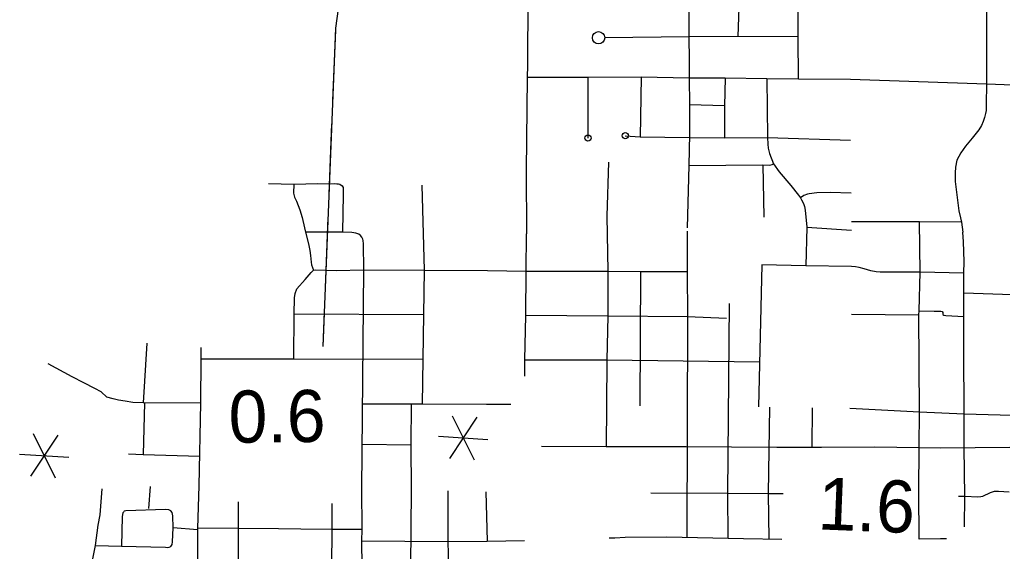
# Model space of a CAD drawing. Extents: x 1366406 to 1373462, y 376856 to 381998.
# Drawn here: x 1369241.5 to 1369331.1, y 379974.8 to 380023.3 of the extents above; entities that cross this region are included whole.
import ezdxf

# ---------------------------------------------------------------- set-up
doc = ezdxf.new("R2010")
doc.units = 0
for name, color, linetype in [('33', 7, 'Continuous'), ('43', 7, 'Continuous'), ('48', 7, 'Continuous')]:
    doc.layers.add(name, color=color, linetype=linetype)

msp = doc.modelspace()

# ---------------------------------------------------------------- linework, layer by layer
at = {"layer": '33'}
for points in [[(1369307.085, 380042.984), (1369307.105, 380040.757), (1369307.055, 380036.923), (1369307.016, 380032.818), (1369307.052, 380028.647), (1369307.064, 380024.428), (1369306.983, 380021.764)], [(1369329.728, 380043.361), (1369329.705, 380038.326), (1369329.648, 380031.144), (1369329.645, 380024.267), (1369329.639, 380017.427), (1369329.612, 380015.619), (1369329.585, 380015.032), (1369329.538, 380014.76), (1369329.443, 380014.38), (1369329.319, 380014.032), (1369329.164, 380013.665), (1369328.917, 380013.285), (1369328.33, 380012.508), (1369327.721, 380011.784), (1369327.277, 380011.182), (1369326.929, 380010.492), (1369326.794, 380009.874), (1369326.761, 380009.365), (1369326.778, 380008.563), (1369327.117, 380005.879), (1369327.25, 380005.241), (1369327.357, 380004.838), (1369327.484, 380003.946)], [(1369312.516, 380017.887), (1369312.458, 380021.753), (1369312.485, 380024.346), (1369312.503, 380028.563), (1369312.438, 380032.761), (1369312.54, 380036.802), (1369312.639, 380040.705)], [(1369302.478, 380028.724), (1369302.547, 380017.974), (1369302.578, 380015.537), (1369302.579, 380012.87), (1369302.509, 380010.019), (1369302.374, 380004.347)], [(1369287.851, 380025.364), (1369287.799, 380019.154), (1369287.787, 380018.052), (1369287.702, 380009.57), (1369287.716, 380003.802)], [(1369312.458, 380021.753), (1369306.983, 380021.764), (1369302.532, 380021.758), (1369294.852, 380021.665)], [(1369332.066, 380017.346), (1369329.639, 380017.427), (1369317.254, 380017.859), (1369312.516, 380017.887), (1369309.619, 380017.934), (1369305.829, 380017.977), (1369302.547, 380017.974), (1369298.155, 380018.056), (1369293.296, 380018.033), (1369291.822, 380018.041), (1369287.787, 380018.052)], [(1369293.296, 380018.033), (1369293.319, 380012.517)], [(1369298.155, 380018.056), (1369298.09, 380012.624)], [(1369305.829, 380017.977), (1369305.768, 380015.447), (1369305.77, 380012.533)], [(1369309.619, 380017.934), (1369309.684, 380012.561), (1369309.705, 380011.978), (1369309.743, 380011.595), (1369309.86, 380011.12), (1369310.23, 380010.162), (1369310.755, 380009.435), (1369311.814, 380008.21), (1369312.488, 380007.304), (1369312.676, 380007.058), (1369312.776, 380006.879), (1369312.969, 380006.542), (1369313.043, 380006.273), (1369313.114, 380005.953), (1369313.265, 380004.389)], [(1369305.768, 380015.447), (1369302.578, 380015.537)], [(1369296.72, 380012.731), (1369298.09, 380012.624), (1369302.57, 380012.561), (1369305.77, 380012.533), (1369309.684, 380012.561), (1369317.238, 380012.324)], [(1369295.183, 380010.333), (1369295.048, 380005.399), (1369295.133, 380000.376), (1369295.14, 379996.295), (1369295.053, 379992.297), (1369295.005, 379988.139), (1369294.988, 379984.395)], [(1369302.509, 380010.019), (1369309.266, 380010.075), (1369309.879, 380010.049), (1369310.103, 380010.096), (1369310.23, 380010.162)], [(1369309.266, 380010.075), (1369309.335, 380005.311)], [(1369264.217, 380008.363), (1369266.531, 380008.32), (1369268.699, 380008.378), (1369269.901, 380008.354), (1369270.224, 380008.364), (1369270.447, 380008.35), (1369270.6, 380008.351), (1369270.711, 380008.323), (1369270.916, 380008.178), (1369271.018, 380008.018), (1369271.023, 380007.762), (1369271.018, 380007.362), (1369270.972, 380003.936)], [(1369266.531, 380008.32), (1369266.51, 380007.494), (1369266.589, 380007.121), (1369266.77, 380006.752), (1369267.058, 380005.978), (1369267.294, 380005.269), (1369267.492, 380004.348), (1369267.579, 380003.944), (1369267.849, 380002.875), (1369267.998, 380002.266), (1369268.047, 380001.802), (1369268.102, 380001.215), (1369268.147, 380000.973), (1369268.307, 380000.489)], [(1369278.235, 379988.249), (1369278.302, 379992.353), (1369278.415, 380000.486), (1369278.213, 380008.213)], [(1369317.3, 380007.51), (1369315.379, 380007.57), (1369314.168, 380007.534), (1369313.486, 380007.439), (1369313.308, 380007.393), (1369313.001, 380007.295), (1369312.676, 380007.058)], [(1369313.265, 380004.389), (1369313.166, 380000.858)], [(1369313.265, 380004.389), (1369317.331, 380004.113)], [(1369327.357, 380004.838), (1369323.535, 380004.885), (1369317.328, 380004.881)], [(1369323.502, 379975.947), (1369323.473, 379980.296), (1369323.498, 379984.334), (1369323.532, 379987.56), (1369323.473, 379996.4), (1369323.496, 379996.765), (1369323.572, 380000.29), (1369323.535, 380004.885)], [(1369272.759, 379973.466), (1369272.735, 379975.812), (1369272.757, 379976.834), (1369272.733, 379980.532), (1369272.895, 380000.506), (1369272.885, 380002.876), (1369272.833, 380003.176), (1369272.824, 380003.289), (1369272.709, 380003.48), (1369272.596, 380003.64), (1369272.446, 380003.762), (1369272.187, 380003.86), (1369271.803, 380003.925), (1369270.972, 380003.936), (1369267.579, 380003.944)], [(1369287.579, 379990.822), (1369287.565, 379992.295), (1369287.673, 379996.355), (1369287.691, 380000.394), (1369287.716, 380003.802)], [(1369302.365, 380004.038), (1369302.359, 380000.367), (1369302.389, 379996.232), (1369302.315, 379976.1)], [(1369327.63, 379977.063), (1369327.649, 379979.871), (1369327.595, 379984.312), (1369327.57, 379996.246), (1369327.577, 379998.403), (1369327.573, 380000.192), (1369327.596, 380001.278), (1369327.54, 380003.058), (1369327.484, 380003.946)], [(1369309.148, 380000.968), (1369308.85, 379988.01)], [(1369313.166, 380000.858), (1369309.148, 380000.968)], [(1369317.322, 380000.816), (1369313.166, 380000.858)], [(1369327.573, 380000.192), (1369323.572, 380000.29), (1369319.947, 380000.306), (1369319.588, 380000.329), (1369319.079, 380000.401), (1369318.472, 380000.602), (1369318.033, 380000.721), (1369317.695, 380000.776), (1369317.322, 380000.816)], [(1369266.53, 379992.38), (1369266.568, 379996.476), (1369266.594, 379997.961), (1369266.656, 379998.363), (1369266.804, 379998.772), (1369267.558, 379999.614), (1369268.115, 380000.274), (1369268.307, 380000.489), (1369268.523, 380000.507), (1369270.394, 380000.445), (1369272.895, 380000.506), (1369278.415, 380000.486), (1369284.184, 380000.451), (1369287.691, 380000.394), (1369295.133, 380000.376), (1369298.118, 380000.362), (1369302.359, 380000.367)], [(1369298.127, 380000.299), (1369298.118, 380000.362), (1369298.035, 379988.097)], [(1369327.577, 379998.403), (1369331.983, 379998.273), (1369342.02, 379997.853), (1369347.233, 379997.601), (1369352.351, 379997.429), (1369357.42, 379997.201), (1369362.517, 379996.954)], [(1369306.193, 379997.445), (1369306.031, 379980.155), (1369306.065, 379976.025)], [(1369278.358, 379996.408), (1369266.568, 379996.476)], [(1369305.946, 379996.071), (1369302.389, 379996.232), (1369295.14, 379996.295), (1369287.673, 379996.355)], [(1369317.327, 379996.474), (1369323.473, 379996.4)], [(1369323.496, 379996.765), (1369324.863, 379996.753), (1369325.272, 379996.735), (1369325.455, 379996.731), (1369325.579, 379996.715), (1369325.654, 379996.63), (1369325.665, 379996.446), (1369325.74, 379996.361), (1369325.93, 379996.341), (1369327.57, 379996.246)], [(1369253.127, 379993.825), (1369252.809, 379988.369)], [(1369258.06, 379993.431), (1369258.056, 379992.39), (1369258.015, 379988.358), (1369257.869, 379980.81)], [(1369258.015, 379988.358), (1369252.809, 379988.369), (1369251.867, 379988.404), (1369251.148, 379988.522), (1369250.566, 379988.624), (1369250.069, 379988.753), (1369249.476, 379988.893), (1369248.976, 379989.377), (1369248.407, 379989.679), (1369247.391, 379990.191), (1369246.332, 379990.75), (1369244.157, 379991.924)], [(1369258.056, 379992.39), (1369266.53, 379992.38), (1369278.302, 379992.353)], [(1369287.565, 379992.295), (1369295.053, 379992.297), (1369308.945, 379992.127)], [(1369252.931, 379988.386), (1369252.795, 379983.685)], [(1369286.301, 379988.244), (1369284.09, 379988.223), (1369278.235, 379988.249), (1369277.215, 379988.252), (1369272.796, 379988.266)], [(1369277.215, 379988.252), (1369277.183, 379984.563), (1369277.211, 379980.456), (1369277.154, 379973.425)], [(1369309.853, 379987.995), (1369309.735, 379980.132), (1369309.806, 379975.944)], [(1369313.763, 379984.334), (1369313.786, 379987.939)], [(1369317.177, 379987.891), (1369323.532, 379987.56), (1369327.583, 379987.394), (1369336.308, 379987.137)], [(1369272.766, 379984.615), (1369277.183, 379984.563)], [(1369289.104, 379984.44), (1369294.988, 379984.395), (1369302.28, 379984.388), (1369310.518, 379984.348), (1369314.593, 379984.331), (1369319.467, 379984.366), (1369325.448, 379984.276), (1369331.763, 379984.349), (1369332.303, 379984.314), (1369335.327, 379984.311), (1369338.659, 379984.311), (1369341.144, 379984.095), (1369343.947, 379983.711), (1369346.115, 379983.665), (1369348.882, 379983.67), (1369352.32, 379983.786)], [(1369251.453, 379983.729), (1369252.795, 379983.685), (1369257.953, 379983.515)], [(1369247.118, 379959.459), (1369247.735, 379970.162), (1369248.027, 379972.715), (1369248.165, 379973.858), (1369248.46, 379975.383), (1369248.714, 379977.22), (1369248.874, 379978.158), (1369249.077, 379980.553)], [(1369253.451, 379980.745), (1369253.272, 379978.753)], [(1369257.869, 379980.81), (1369257.757, 379976.943), (1369257.754, 379976.815), (1369257.755, 379973.597), (1369257.735, 379972.678), (1369257.745, 379970.699), (1369257.709, 379968.827), (1369257.653, 379964.775), (1369257.6, 379960.679), (1369257.6, 379959.637), (1369257.605, 379958.677)], [(1369280.566, 379980.347), (1369280.558, 379975.747), (1369280.604, 379973.422)], [(1369284.011, 379980.274), (1369284.138, 379975.778)], [(1369299.06, 379980.177), (1369306.031, 379980.155), (1369309.735, 379980.132), (1369311.109, 379980.119)], [(1369327.076, 379979.869), (1369327.649, 379979.871), (1369328.856, 379979.812), (1369329.106, 379979.838), (1369329.308, 379979.883), (1369330.009, 379980.221), (1369330.363, 379980.315), (1369330.728, 379980.325), (1369331.692, 379980.282)], [(1369261.454, 379979.347), (1369261.455, 379973.536), (1369261.411, 379972.707), (1369261.368, 379964.713), (1369261.32, 379960.696), (1369261.24, 379958.584)], [(1369248.46, 379975.383), (1369250.826, 379975.32), (1369254.848, 379975.233), (1369254.993, 379975.208), (1369255.175, 379975.229), (1369255.326, 379975.298), (1369255.451, 379975.467), (1369255.474, 379975.72), (1369255.534, 379976.975), (1369255.513, 379978.074), (1369255.47, 379978.241), (1369255.426, 379978.389), (1369255.333, 379978.526), (1369255.143, 379978.619), (1369254.825, 379978.65), (1369251.229, 379978.534), (1369251.08, 379978.506), (1369251.023, 379978.45), (1369250.952, 379978.349), (1369250.899, 379978.021), (1369250.826, 379975.32)], [(1369269.975, 379972.764), (1369269.989, 379973.448), (1369270.01, 379976.835), (1369270.031, 379979.212)], [(1369257.754, 379976.815), (1369255.534, 379976.975)], [(1369272.757, 379976.834), (1369270.01, 379976.835), (1369267.162, 379976.854), (1369265.119, 379976.907), (1369257.757, 379976.943)], [(1369272.735, 379975.812), (1369280.558, 379975.747), (1369284.138, 379975.778), (1369287.53, 379975.82)], [(1369310.981, 379975.917), (1369307.496, 379975.997), (1369300.514, 379976.137), (1369296.704, 379976.107), (1369295.778, 379976.046), (1369295.243, 379976.05)], [(1369325.973, 379975.972), (1369325.433, 379975.973), (1369323.502, 379975.947)]]:
    msp.add_lwpolyline(points, dxfattribs=at)
for centre, radius in [((1369294.287, 380021.665), 0.566), ((1369293.319, 380012.517), 0.281), ((1369296.72, 380012.731), 0.281)]:
    msp.add_circle(centre, radius, dxfattribs=at)
at = {"layer": '43'}
for points in [[(1369269.186, 379993.518), (1369270.344, 380022.526), (1369271.535, 380031.154)], [(1369270.082, 380015.954), (1369270.337, 380022.364)], [(1369269.74, 380007.407), (1369269.996, 380013.817)], [(1369269.399, 379998.86), (1369269.655, 380005.27)], [(1369269.186, 379993.518), (1369269.314, 379996.723)]]:
    msp.add_lwpolyline(points, dxfattribs=at)
at = {"layer": '48'}
for p, q in [((1369283.204, 379987.066), (1369280.715, 379983.317)), ((1369280.959, 379987.207), (1369282.96, 379983.177)), ((1369242.791, 379985.586), (1369244.793, 379981.556)), ((1369245.037, 379985.446), (1369242.547, 379981.697)), ((1369279.714, 379985.333), (1369284.205, 379985.051)), ((1369241.546, 379983.712), (1369246.037, 379983.431))]:
    msp.add_line(p, q, dxfattribs=at)

# ---------------------------------------------------------------- texts
for s, rotation, p in [('0.6', 0.60145, (1369260.603, 379984.734)), ('1.6', 357.71665, (1369314.199, 379976.85))]:
    msp.add_text(s, height=4.752, rotation=rotation, dxfattribs=at).set_placement(p)

doc.saveas('drawing.dxf')
